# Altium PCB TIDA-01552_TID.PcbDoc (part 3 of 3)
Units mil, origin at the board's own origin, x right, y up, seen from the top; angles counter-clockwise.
Board outline 6250 x 2150 mil, 4 copper layers (Top Layer, Signal Layer 1, Signal Layer 2, Bottom Layer), stack 62.6 mil thick; 251 components, 249 nets, 926 pads, 730 vias.
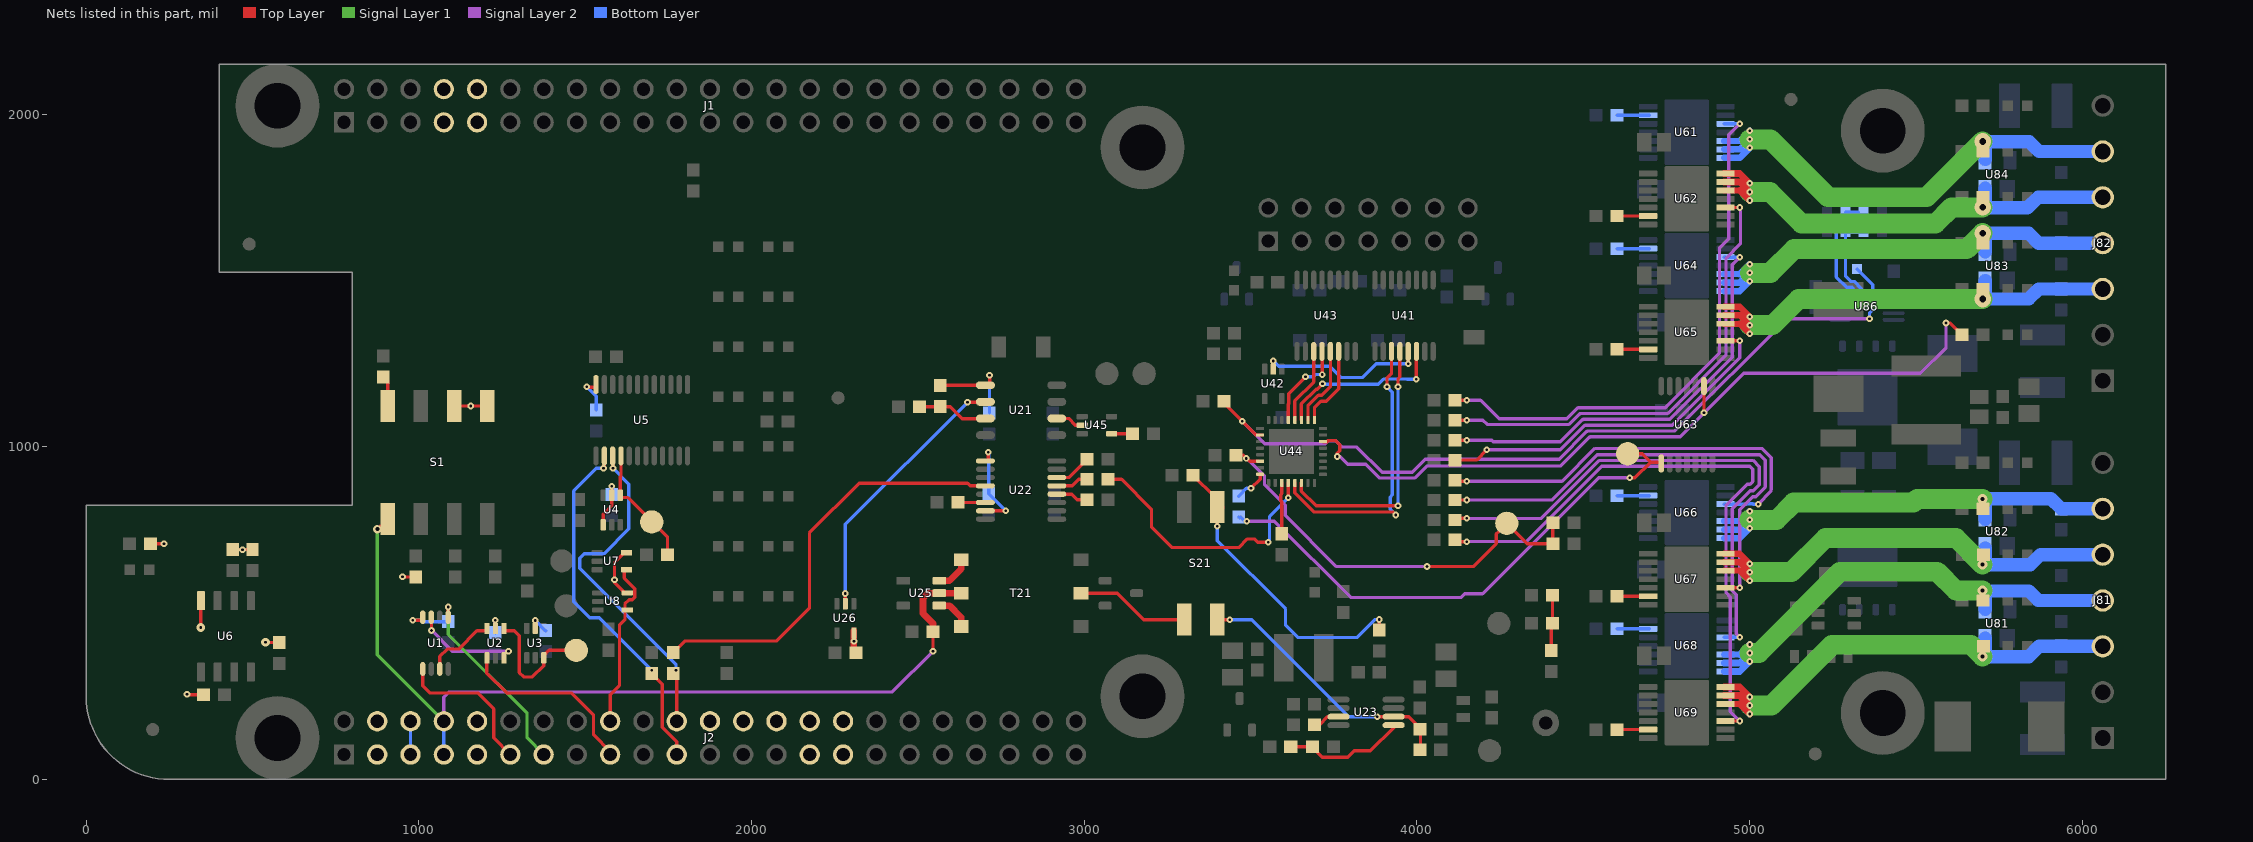
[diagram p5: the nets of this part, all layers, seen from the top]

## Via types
v1: diameter 20, hole 8, Top Layer to Bottom Layer, tented both sides, 418 vias
v2: diameter 19.68, hole 7.87, Top Layer to Bottom Layer, 77 vias
v3: diameter 30, hole 12, Top Layer to Bottom Layer, tented both sides, 73 vias
v4: diameter 19.68, hole 7.87, Top Layer to Bottom Layer, tented both sides, 48 vias
v5: diameter 39.37, hole 19.68, Top Layer to Bottom Layer, 36 vias
v6: diameter 26, hole 12, Top Layer to Bottom Layer, tented both sides, 31 vias
v7: diameter 20, hole 7.87, Top Layer to Bottom Layer, tented both sides, 12 vias
v8: diameter 20, hole 8, Top Layer to Bottom Layer, 12 vias
v9: diameter 30, hole 12, Top Layer to Bottom Layer, 9 vias
v10: diameter 32, hole 16, Top Layer to Bottom Layer, tented both sides, 8 vias
v11: diameter 50, hole 20, Top Layer to Bottom Layer, tented both sides, 4 vias
v12: diameter 26, hole 8, Top Layer to Bottom Layer, tented both sides, 2 vias

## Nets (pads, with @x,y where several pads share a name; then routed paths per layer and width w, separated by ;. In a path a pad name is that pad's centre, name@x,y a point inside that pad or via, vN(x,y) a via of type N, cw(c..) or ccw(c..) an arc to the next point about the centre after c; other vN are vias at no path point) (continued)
NetR17_2: R17.2 TP1.1 U4.4 U5.4 | length 380.6
  Top Layer w10: U5.4@1607.5,980.59 1607.5,911.5 1605.59,909.59 1605.59,847.4 1628.6,847.4 TP1.1@1700,776 ; TP1.1@1700,774 TP1.1@1700,776 ; R17.2@1747.5,675 1747.5,728.5 TP1.1@1700,776
NetR18_2: R18.2 S1.8 | length 92.4
  Top Layer w10: R18.2@893,1209.5 906,1196.5 S1.8@906,1122.5
NetR23_2: R23.2 U22.14 | length 122.1
  Top Layer w10: U22.14@2909.41,907.5 2953,907.5 R23.2@3008.5,963
NetR24_2: R24.2 U22.13 | length 107.2
  Top Layer w10: U22.13@2909.41,882.5 2963.5,882.5 2983,902 R24.2@3008.5,902
NetR25_2: R25.2 U22.12 | length 105.9
  Top Layer w10: U22.12@2909.41,857.5 2962.5,857.5 2979,841 R25.2@3008.5,841
NetR26_1: R26.1 U22.6 | length 90.3
  Top Layer w10: R26.1@2620.5,833 2621,832.5 U22.6@2710.59,832.5
NetR27_2: R27.2 R33.2 U23.5 | length 353.8
  Top Layer w10: R27.2@3633.62,98 3683.5,98 3714.6,66.43 3791.43,66.43 3811,86 3859.94,86 3929.68,155.74 U23.5@3929.68,163.3
NetR28_1: R28.1 R34.2 S21.2 U23.6 | length 809.7
  Top Layer w10: S21.2@3400,480.51 v1@3436.48,480.51 ; v1(3880.51,189) 3929.57,189 U23.6@3929.68,188.89 3975.11,188.89 4010.5,153.5 R34.2@4010.5,89
  Bottom Layer w10: v1(3437,479.99) 3504.01,479.99 3795,189 v1(3880.51,189)
NetR29_1: R29.1 R35.2 S21.3 | length 931.7
  Top Layer w10: R35.2@3326.5,915 3393.59,847.91 3393.59,841.54 3417.13,818 3400,800.87 v1(3400,761) ; R29.1@3887,449.5 v1(3887,481)
  Bottom Layer w10: v1(3400,761) 3400,717.53 3605,512.53 3605,464 3642,427 3821,427 3875,481 v1(3887,481)
NetR31_2: R31.2 U23.3 | length 82.7
  Top Layer w10: R31.2@3691.5,165 3707,165 3730.89,188.89 U23.3@3764.32,188.89
NetR43_2: R43.2 U44.11 | length 155.9
  Top Layer w10: R43.2@3593,738.5 3593.47,738.97 3593.47,834.18 3590.28,837.37 3590.28,856.32 3593.47,859.51 U44.11@3593.47,891.51
NetR44_1: R44.1 U45.4 | length 69.3
  Top Layer w10: U45.4@3075.4,1039.41 3075.81,1039 R44.1@3144.5,1039
NetR61_1: R61.1 U61.13 | length 97.3
  Bottom Layer w10: R61.1@4601.5,1996.3 U61.13@4698.76,1996.3
NetR62_1: R62.1 U62.13 | length 97.3
  Top Layer w10: R62.1@4601.5,1693.67 U62.13@4698.76,1693.67
NetR63_2: R63.2 U61.3 | length 1660.9
  Top Layer w10: R63.2@4114.5,1140 v1(4150,1140)
  Signal Layer 2 w10: v1(4150,1140) 4191,1140 4246.5,1084.5 4449.76,1084.5 4481.76,1116.5 4483.26,1116.5 4484.26,1117.5 4745.87,1117.5 4909,1280.63 4909,1597.25 4937.33,1625.58 4937.33,1938.07 v1(4970,1970.74)
  Bottom Layer w10: U61.3@4923.2,1970.74 v1(4970,1970.74)
NetR64_2: R64.2 U62.3 | length 1412.3
  Top Layer w10: R64.2@4114.5,1080 v1(4150,1080) ; U62.3@4923.2,1719.22 v1(4970,1719.22)
  Signal Layer 2 w10: v1(4150,1080) 4198,1080 4211,1067 4457.01,1067 4489.01,1099 4490.51,1099 4491.51,1100 4753.12,1100 4929,1275.88 4929,1567 4972.1,1610.1 v1@4972.1,1717.13
NetR65_2: R65.2 U44.8 | length 100.1
  Top Layer w10: v1(3501,875) 3528.51,902.51 U44.8@3528.51,917.1
  Bottom Layer w10: R65.2@3464.04,851.74 3487.3,875 v1(3501,875)
NetR66_1: R66.1 U64.13 | length 97.3
  Bottom Layer w10: R66.1@4601.5,1595.63 U64.13@4698.76,1595.63
NetR67_1: R67.1 U65.13 | length 97.3
  Top Layer w10: R67.1@4601.5,1293 U65.13@4698.76,1293
NetR68_2: R68.2 U64.3 | length 1296.7
  Top Layer w10: R68.2@4114.5,1020 v1(4150,1020)
  Signal Layer 2 w10: v1(4150,1020) 4225,1020 4229.5,1015.5 4430.25,1015.5 4496.25,1081.5 4497.76,1081.5 4498.76,1082.5 4760.37,1082.5 4947.13,1269.26 4947.13,1547.2 v1(4970,1570.07)
  Bottom Layer w10: U64.3@4923.2,1570.07 v1(4970,1570.07)
NetR69_2: R69.2 U65.3 | length 1080.8
  Top Layer w10: R69.2@4114.5,960 4179,960 v1(4210,991) ; U65.3@4923.2,1318.56 v1(4970,1318.56)
  Signal Layer 2 w10: v1(4210,991) 4430.5,991 4503.5,1064 4505.01,1064 4506.01,1065 4767.62,1065 4970,1267.38 v1(4970,1318.56)
NetR70_1: R70.1 U66.13 | length 97.3
  Bottom Layer w10: R70.1@4601.5,853.3 U66.13@4698.76,853.3
NetR71_1: R71.1 U67.13 | length 97.3
  Top Layer w10: R71.1@4601.5,550.67 U67.13@4698.76,550.67
NetR73_2: R73.2 U66.3 | length 1263.4
  Top Layer w10: R73.2@4114.5,900 4118.5,896 v1(4150,896)
  Signal Layer 2 w10: v1(4150,896) 4436.01,896 4535.01,995 5036.75,995 5064.5,967.25 5064.5,871.75 5064,871.25 5064,866 v1(5025.74,827.74)
  Bottom Layer w10: U66.3@4923.2,827.74 4989.36,827.74 4990.68,829.06 5009.32,829.06 5010.64,827.74 v1(5025.74,827.74)
NetR74_2: R74.2 U67.3 | length 1463.6
  Top Layer w10: R74.2@4114.5,840 v1(4150,840) ; U67.3@4923.2,576.22 v1(4970,576.22)
  Signal Layer 2 w10: v1(4150,840) 4404.75,840 4541.25,976.5 5030.5,976.5 5047,960 5047,879 5018.24,850.24 5009.24,850.24 4970,811 v1(4970,576.22)
NetR76_1: R76.1 U68.13 | length 97.3
  Bottom Layer w10: R76.1@4601.5,452.63 U68.13@4698.76,452.63
NetR77_1: R77.1 U69.13 | length 97.3
  Top Layer w10: R77.1@4601.5,150 U69.13@4698.76,150
NetR78_2: R78.2 U68.3 | length 1605
  Top Layer w10: R78.2@4114.5,780 4119.5,785 v1(4150,785)
  Signal Layer 2 w10: v1(4150,785) 4150.5,784.5 4374,784.5 4548.5,959 5010,959 5029,940 5029,886 5010.74,867.74 5001.74,867.74 4947.5,813.5 4947.5,566.9 4959.5,554.9 4959.5,437.57 v1(4970,427.07)
  Bottom Layer w10: U68.3@4923.2,427.07 v1(4970,427.07)
NetR79_2: R79.2 U69.3 | length 1853
  Top Layer w10: R79.2@4114.5,720 4119.5,715 v1(4150,715) ; U69.3@4923.2,175.56 v1(4970,175.56)
  Signal Layer 2 w10: v1(4150,715) 4150.5,715.5 4329.75,715.5 4555.75,941.5 5000,941.5 5009,932.5 5009,895.5 5001.03,887.53 4992.53,887.53 4929,824 4929,560.66 4942,547.66 4942,203.56 v1(4970,175.56)
NetR80_1: R80.1 R81.2 R82.2 | length 149.3
  Top Layer w10: R80.1@4404,387.5 4404,466.5 R81.2@4407.5,470 ; 4407.5,488.7 R82.2@4407.5,554
NetR92_1: R92.1 R93.2 U86.4 | length 399.1
  Bottom Layer w10: U86.4@5271.29,1440.68 5305.72,1440.68 5317.63,1452.59 5317.63,1468.15 5306.63,1479.15 5291.07,1479.15 5260.13,1510.1 5260.13,1665.33 5267.67,1672.87 5288,1672.87 R92.1@5288,1705 R93.2@5327,1705
NetR94_1: R94.1 R95.2 U86.3 | length 339.7
  Bottom Layer w10: U86.3@5271.29,1421 5277.2,1421 5277.2,1421.91 5312.22,1421.91 5335.5,1445.19 5335.5,1475.55 5314.03,1497.02 5302.98,1497.02 5288,1512 R94.1@5288,1645 R95.2@5327,1645
NetR96_2: R96.2 U86.7 | length 170.6
  Bottom Layer w10: R96.2@5323,1534 5370,1487 5370,1449 5378.31,1440.68 U86.7@5432.71,1440.68
NetS21_1: S21.1 T21.2 | length 320.9
  Top Layer w10: 3012,560 3099,560 3178.49,480.51 S21.1@3300,480.51
NetT21_4: T21.4 U25.3 | length 114.5
  Top Layer w20: U25.3@2557.24,597.4 2594.4,597.4 2630,633 T21.4@2630,660
NetT21_6: T21.6 U25.1 | length 114.5
  Top Layer w20: U25.1@2557.24,522.6 2594.4,522.6 2630,487 T21.6@2630,460
NetTP2_1: TP2.1 U2.4 U3.3 | length 383.1
  Top Layer w10: 1263.46,447.4 1287.27,447.4 1302.13,432.54 1302.13,321.53 1315.53,308.13 1341.43,308.13 1375.59,342.29 1375.59,372.6 1390.99,388 TP2.1@1473,388
NetU1_3: U1.3 U2.6 | length 202.5
  Top Layer w10: U1.3@1062.8,341.1 1062.8,369.81 1085.11,392.13 1119.41,392.13 1174.69,447.4 U2.6@1204.41,447.4
NetU1_7: U1.7 U2.3 | length 297.5
  Top Layer w10: U1.7@1037.2,487.76 1038,486.96 v1(1038,448)
  Signal Layer 2 w10: v1(1038,448) 1100.72,385.28 v1(1269.39,385.28)
NetU21_2: U21.2 U26.2 | length 831.5
  Top Layer w10: U26.2@2282,521.4 v1(2282,559) ; v1(2649,1134) 2714.51,1134 U21.2@2715.51,1135
  Bottom Layer w10: v1(2282,559) 2282,767 v1(2649,1134)
NRST: U41.13 U42.2 | length 503.1
  Top Layer w10: U42.2@3568,1243.13 v1(3568,1258) ; v1(3973.5,1250) U41.13@3973.5,1294.59
  Bottom Layer w10: v1(3568,1258) 3584,1242 3738,1242 3772,1208 3835.65,1208 3877.65,1250 v1(3973.5,1250)
P_GOOD: R46.2 U44.2 U86.8 | length 2401.6
  Top Layer w10: R46.2@3416.97,1134.47 v1(3475,1076.44) 3516.22,1035.21 U44.2@3528.51,1035.21 U44.2@3533.24,1035.21
  Signal Layer 2 w10: v1(3475,1076.44) 3542.44,1009 3724.18,1009 3733.52,1018.34 3755.5,1018.34 3774.71,999.13 3819.19,999.13 3894.82,923.5 3985.32,923.5 4024.82,963 4427.25,963 4510.75,1046.5 4512.26,1046.5 4513.26,1047.5 4774.86,1047.5 5112.36,1385 v1(5360,1385)
  Bottom Layer w10: v1(5360,1385) 5360,1401 5380,1421 U86.8@5432.71,1421
PWR_BUT: J2.9
RST_N: U21.6 U45.2 | length 104.4
  Top Layer w10: U21.6@2904.49,1085 2953,1085 2973,1065 U45.2@3000.6,1065
RXD: U41.12 U44.14 | length 807.1
  Top Layer w10: U44.14@3652.53,891.51 3652.53,866.92 3696.44,823 3709,823 v1(3943,823) ; v1(3943,1180) 3943,1204.49 3948.5,1209.99 U41.12@3948.5,1294.59
  Bottom Layer w10: v1(3943,823) v1(3943,1180)
SCLK: R5.2 U22.4 | length 1292.6
  Top Layer w10: R5.2@1764,381.5 1798.5,416 2074.78,416 2173.9,515.12 2173.9,740.9 2323,890 2649,890 2656.5,882.5 U22.4@2710.59,882.5
SCLK_ISO: R24.1 U44.12 | length 815.2
  Top Layer w10: R24.1@3071.5,902 3112,902 3201.78,812.22 3201.78,759.94 3264.6,697.13 3464.78,697.13 3490.53,722.87 3511.13,722.87 3521,713 v1(3553,713) ; v1(3613.16,846.84) U44.12@3613.16,891.51
  Bottom Layer w10: v1@3552.87,713 3556.87,717 3556.87,790.56 v1(3613.16,846.84)
SHIFTCLK: R65.1 TP61.1 U63.8 | length 1620.5
  Top Layer w10: TP61.1@4633,979 4677,979 4702.06,953.94 ; v8(4639,907) 4655.11,907 4702.06,953.94 ; U63.8@4734.23,953.94 4702.06,953.94
  Signal Layer 2 w10: v1(3488,776) 3571.44,776 3800.32,547.13 4133.13,547.13 4144,558 4197,558 4546,907 v8(4639,907)
  Bottom Layer w10: R65.1@3464.04,788.75 3466.55,786.25 3469.3,789 3482.3,776 v1(3488,776)
SHIFTSTRT: R45.2 U44.22 U63.2 | length 2328.8
  Top Layer w10: U44.22@3717.49,1015.53 3730.18,1015.53 3733.53,1018.87 3754.66,1018.87 3767.87,1005.66 3767.87,988.53 3760,980.65 v1(3760,971) ; U63.2@4862,1178.35 4862.5,1177.85 v1(4862.5,1102.5) ; v1(5590,1372) 5602.95,1372 R45.2@5638.5,1336.44
  Signal Layer 2 w10: v1(3760,971) 3767.71,971 3791.71,947 3846.57,947 3887.57,906 3992.57,906 4028.57,942 4431,942 4518,1029 4519.51,1029 4520.51,1030 4791,1030 4862,1101 4862.5,1101.5 v1(4862.5,1102.5) 4863,1102 4982,1221 5513,1221 5590,1298 v1(5590,1372)
SPI0_CS: J2.17 U2.1 | length 564.7
  Top Layer w10: U2.1@1204.41,372.6 1204.41,319.75 1264.16,260 1458,260 1525,193 1525,134 1575,84 J2.17@1575,75
SPI0_D0: J2.21 R3.1 U5.2 | length 1088.5
  Top Layer w10: v1@1557.5,937.5 U5.2@1557.5,980.59 ; R3.1@1700,318.5 1731.61,286.89 1731.61,157.03 1775,113.64 J2.21@1775,75
  Bottom Layer w10: v1(1555,935) 1533,935 1465.25,867.25 1465.25,534.21 1513.39,486.07 1542.25,486.07 v1(1700,328.33)
SPI0_D1: J2.18 U7.4 U8.4 | length 504.9
  Top Layer w10: J2.18@1575,175 1575,254.37 1603,282.37 1603,464 1619.4,480.4 1619.4,509.41 1619.4,527.52 1631.72,539.84 1641.47,539.84 1649.01,547.38 1649.01,573.8 1617.4,605.4 U7.4@1617.4,630.41
SPI0_SCLK: J2.22 R5.1 U5.3 | length 1035.9
  Top Layer w10: U5.3@1582.5,980.59 1582.5,935.99 v1(1583.49,935) ; R5.1@1764,318.5 1775,307.5 J2.22@1775,175
  Bottom Layer w10: v1(1583.49,935) 1631,887.49 1631,753 1556.5,678.5 1496.68,678.5 1483.13,664.95 1483.13,634.81 1773,344.93 v1@1773,329.25
  other v1: 1773,328
SPI1_CS0: J2.28
SPI1_D0: J2.29
SPI1_D1: J2.30
SPI1_SCLK: J2.31
SUPPLY_DIV: C66.1 R72.1 R75.2 TP62.1 U44.6 | length 1252.9
  Top Layer w10: C66.1@3455.5,975 3478.33,975 3496.85,956.47 U44.6@3523.79,956.47 ; v1(4030,640) 4168.84,640 4238,709.16 4238,738 4245.04,745.04 ; 4294.96,745.04 4331,709 R72.1@4408.5,709 R75.2@4408.5,772
  Signal Layer 2 w10: v1(3487,965) 3488.33,965 3541.75,911.58 3541.75,885.9 3603.68,823.97 3603.68,794.32 3758,640 v1(4030,640)
SYS_5V: C31.1 J2.7 J2.8 S1.1 T21.5 U25.2 | length 2666.5
  Top Layer w10: v6(875,752.5) S1.1@884,761.5 ; v1(2545.5,385.5) C31.1@2545.5,444
  Top Layer w20: C31.1@2545.5,444 2545.5,468.64 2515,499.13 2515,545.32 2529.68,560 2557.24,560 T21.5@2630,560
  Signal Layer 2 w10: J2.8@1075,175 1075,247 1091,263 2422.99,263 v1(2545.5,385.5)
  Signal Layer 1 w10: v6(875,752.5) 875,375 J2.8@1075,175
  Bottom Layer w10: J2.7@1075,75 J2.8@1075,175
SYS_RESETN: J2.10
TCK: U43.14 U44.25 | length 214.8
  Top Layer w10: U44.25@3691.9,1080.49 3691.9,1117.49 3711.28,1136.87 3726.87,1136.87 3764.5,1174.5 3764.5,1256.05
TDI/TCLK: U41.14 U44.27 | length 518.7
  Top Layer w10: U44.27@3652.53,1080.49 3652.53,1128.67 3696.48,1172.62 3699.9,1172.62 3716,1188.72 v1(3716,1189) ; v1(3998,1203) 3998,1294.09 U41.14@3998.5,1294.59
  Bottom Layer w10: v1(3716,1189) 3716.87,1188.13 3883.78,1188.13 3899.2,1203.55 3970.84,1203.55 3970.29,1203 v1(3998,1203)
TDO: U43.11 U44.28 | length 237.6
  Top Layer w10: U44.28@3632.84,1080.49 3632.84,1137.84 3689.5,1194.5 U43.11@3689.5,1294.59
TEST: U43.12 U44.29 | length 281.7
  Top Layer w10: U44.29@3613.16,1080.49 3613.16,1128.35 3614.34,1129.53 3614.34,1159.34 v1(3665,1210) ; U43.12@3714.5,1294.59 3715,1294.09 v1(3715,1217)
  Bottom Layer w10: v1(3665,1210) 3686.5,1210 3693.5,1217 v1(3715,1217)
TIMER4: J1.7
TIMER5: J1.9
TIMER6: J1.10
TIMER7: J1.8
TMS: U43.13 U44.26 | length 248.2
  Top Layer w10: U44.26@3672.21,1080.49 3672.21,1123.08 3703.88,1154.75 3714.1,1154.75 3739.83,1180.48 3739.83,1294.26 U43.13@3739.5,1294.59
TXD: U41.11 U44.13 | length 882
  Top Layer w10: U44.13@3632.84,891.51 3632.84,861.32 3690.17,804 3927,804 v1(3936,795) ; v1(3910,1180) 3910,1207 3923.5,1220.5 U41.11@3923.5,1294.59
  Bottom Layer w10: v1(3910,1180) 3925.5,1164.5 3925.5,855.22 3919.13,848.85 3919.13,811.87 v1(3936,795)
UART1_RXD: J2.26
UART1_TXD: J2.24
UART4_RXD: J2.11 U1.1 | length 459.6
  Top Layer w10: U1.1@1011.61,341.1 1011.61,281.39 1033,260 1177,260 1225,212 1225,125 J2.11@1275,75
UART4_TXD: J2.13 U1.5 | length 602.1
  Top Layer w10: U1.5@1088.39,478.9 v1(1088.39,518.61)
  Signal Layer 1 w10: v1(1088.39,518.61) 1088.39,435.78 1325,199.16 1325,125 J2.13@1375,75
VDD_3V3B: C1.1 C2.1 C3.1 C4.1 C5.1 C6.1 C21.1 C23.1 J2.3 J2.4 R4.2 R8.2 R11.2 R12.2 R13.2 R21.2 R22.2 S1.5 S1.6 U1.8 U2.5 U3.5 U4.1 U4.5 U5.24 U6.8 U7.5 U8.5 U21.1 U22.1 U22.7 U26.5 | length 1655.3
  Top Layer w10: R4.2@193.5,709 v1(234,709) ; v1@304,255 R8.2@352.5,255 ; v12(344,457) 344,523.49 U6.8@345,524.49 ; R12.2@440,691.5 R13.2@481.3,691.5 ; v12@539.5,411.5 C6.1@580,411.5 ; v1(951,609) 951.5,608.5 R11.2@990,608.5 ; v1@982.1,478.9 U1.8@1011.61,478.9 ; S1.6@1106,1122.5 S1.5@1184,1122.5 ; U2.5@1230,447.4 v1(1230,479) ; U3.5@1350,447.4 v1(1350,478) ; v1@1505.59,1179.41 U5.24@1532.5,1179.41 ; U4.1@1554.43,765 1554.41,797.41 1580,823 1580,847.4 v1(1580,881) ; U7.5@1617.4,681.59 1587.8,651.98 1587.8,592.2 U8.5@1619.4,560.59 ; R21.2@2307.59,386.91 R21.2@2313.5,381 ; R22.2@2567,1185 2715.51,1185 v1@2715.51,1214.49 ; U22.7@2710.59,807.5 v1(2764.42,807.5) ; U22.1@2710.59,957.5 2711,957.91 v1(2711,984)
  Top Layer w20: R21.2@2307.59,386.91 U26.5@2307.59,446.6
  Bottom Layer w10: v1@982.1,478.9 1011.61,478.9 1016.02,474.5 C1.1@1088.39,474.5 ; v1(1230,479) 1230,441.56 C2.1@1230.07,441.49 ; v1(1350,478) 1380.5,447.5 C3.1@1382,447.5 ; v1(1505,1180) 1533,1152 C5.1@1533,1110.5 ; v1@2712.49,982.51 C23.1@2712.49,859.02 v1@2764,807.5 ; C21.1@2715,1101.5 v1(2715,1215)
  other v1: 303,256 2308,415 982,479 1587.8,600 470,691 1156,1122.5
  other v12: 539,412
VDD_5V: J2.5 J2.6 | length 100
  Bottom Layer w10: J2.5@975,75 J2.6@975,175
VDD_ADC: J2.32
XRST_N: R2.2 R22.1 U21.3 | length 228.5
  Top Layer w10: R2.2@2504.5,1120 R22.1@2565.5,1120 ; R22.1@2567,1121.5 R22.1@2565.5,1120 ; U21.3@2715.51,1085 2714.51,1084 2632.66,1084 2596.66,1120 R22.1@2565.5,1120
Y0: C81.1 J81.3 R83.2 U69.5 U69.6 U69.7 U81.2 | length 1478.3
  Top Layer w18: U69.5@4923.2,226.74 4970,226.74
  Top Layer w20: U69.6@4923.2,252.33 4968.67,252.33 v1@4999,222 ; U69.7@4923.2,277.92 4970,277.92 v1(5000,247.92) ; 4970,226.74 v1(5000,196.74)
  Signal Layer 1 w60: v1@5000.33,222 5065,222 5248,405 5665.2,405 v3(5700,370.2)
  Bottom Layer w40: U81.2@5707.5,424.69 5707.5,369.26 5838.26,369.26 5869.5,400.5 C81.1@5936,400.5 ; C81.1@5936.29,400.2 J81.3@6061,400.2
  other v1: 5000,222.33
Y1: C82.1 J81.4 R84.2 U68.5 U68.6 U68.7 U81.3 | length 1512.7
  Signal Layer 1 w60: v1(5000,380.3) 5027.59,380.3 5271.67,624.38 5563.62,624.38 5620,568 v3(5700,568)
  Bottom Layer w18: U68.5@4923.2,375.89 4970,375.89
  Bottom Layer w20: U68.7@4923.2,324.71 4970,324.71 v1(5000,354.71) ; U68.6@4923.2,350.3 4970,350.3 v1(5000,380.3) ; 4970,375.89 v1(5000,405.89)
  Bottom Layer w40: U81.3@5707.5,511.31 5707.5,566.74 5838.26,566.74 5866.84,538.16 C82.1@5936,538.16 ; C82.1@5936.16,538 J81.4@6061,538
Y2: C83.1 J81.5 R85.2 U67.5 U67.6 U67.7 U82.2 | length 1460.3
  Top Layer w18: U67.5@4923.2,627.41 4970,627.41
  Top Layer w20: U67.6@4923.2,653 4970,653 v1(5000,623) ; U67.7@4923.2,678.59 4970,678.59 v1(5000,648.59) ; 4970,627.41 v1(5000,597.41)
  Signal Layer 1 w60: v1(5000,623) 5125,623 5227.83,725.83 5619.97,725.83 v3(5700,645.8)
  Bottom Layer w40: U82.2@5707.5,695.69 5707.5,645 5843,645 5873.83,675.83 C83.1@5936,675.83 ; C83.1@5936,675.83 J81.5@6061,675.8
Y3: C84.1 J81.6 R86.2 U66.5 U66.6 U66.7 U82.3 | length 1420.9
  Signal Layer 1 w60: v1(5000,780.97) 5005.34,780.97 5006.06,780.24 5080.24,780.24 5132,832 5492,832 5503.59,843.59 v3(5700,843.59)
  Bottom Layer w18: U66.5@4923.2,776.56 4970,776.56
  Bottom Layer w20: U66.7@4923.2,725.38 4970,725.38 v1(5000,755.38) ; U66.6@4923.2,750.97 4970,750.97 v1(5000,780.97) ; 4970,776.56 v1(5000,806.56)
  Bottom Layer w40: U82.3@5707.5,782.31 U82.3@5707.5,788.31 5707.5,844 5905.5,844 C84.1@5936,813.5 ; C84.1@5937.09,813.59 J81.6@6061,813.59
Y4: C85.1 J82.3 R87.2 U65.5 U65.6 U65.7 U83.2 | length 1421.7
  Top Layer w18: U65.5@4923.2,1369.74 4970,1369.74
  Top Layer w20: U65.6@4923.2,1395.33 4970,1395.33 v1(5000,1365.33) ; U65.7@4923.2,1420.92 4970,1420.92 v1(5000,1390.92) ; 4970,1369.74 v1(5000,1339.74)
  Signal Layer 1 w60: v1(5000,1365.33) 5068.33,1365.33 5147.2,1444.2 v11(5700,1444.2)
  Bottom Layer w40: U83.2@5707.5,1499.69 5707.5,1444.26 5838.26,1444.26 5868.2,1474.2 J82.3@6061,1474.2
Y5: C86.1 J82.4 R88.2 U64.5 U64.6 U64.7 U83.3 | length 1437.2
  Signal Layer 1 w60: v1@5001,1523 5062,1523 5133,1594 5652,1594 v11(5700,1642)
  Bottom Layer w18: U64.5@4923.2,1518.89 4970,1518.89
  Bottom Layer w20: U64.7@4923.2,1467.71 4970,1467.71 v1(5000,1497.71) ; U64.6@4923.2,1493.3 4970,1493.3 v1(5000,1523.3) ; 4970,1518.89 v1(5000,1548.89)
  Bottom Layer w40: U83.3@5707.5,1586.31 5707.5,1641.74 5838.26,1641.74 5868,1612 J82.4@6061,1612
Y6: C87.1 J82.5 R89.2 U62.5 U62.6 U62.7 U84.2 | length 1452.6
  Top Layer w18: U62.5@4923.2,1770.41 4970,1770.41
  Top Layer w20: U62.6@4923.2,1796 4970,1796 v1(5000,1766) ; U62.7@4923.2,1821.59 4970,1821.59 v1(5000,1791.59) ; 4970,1770.41 v1(5000,1740.41)
  Signal Layer 1 w60: v1(5000,1766) 5061,1766 5156,1671 5558.39,1671 5607.18,1719.8 v11(5700,1719.8)
  Bottom Layer w40: U84.2@5707.5,1776.69 U84.2@5707.5,1774.69 5707.5,1718 5835,1718 5866.8,1749.8 J82.5@6061,1749.8
Y7: C88.1 J82.6 R90.2 U61.5 U61.6 U61.7 U84.3 | length 1528.3
  Signal Layer 1 w60: v1(5000,1923.97) 5062.03,1923.97 5236,1750 5531.59,1750 v11@5699.59,1918
  Bottom Layer w18: U61.5@4923.2,1919.56 4970,1919.56
  Bottom Layer w20: U61.7@4923.2,1868.38 4970,1868.38 v1(5000,1898.38) ; U61.6@4923.2,1893.97 4970,1893.97 v1(5000,1923.97) ; 4970,1919.56 v1(5000,1949.56)
  Bottom Layer w40: U84.3@5707.5,1863.31 5707.5,1917 5840,1917 5869.41,1887.59 J82.6@6061,1887.59
  other v11: 5700,1917.59
pads on no net: D41.2 D42.2 FID1.1 FID2.1 FID3.1 FID4.1 FID5.1 J41.4 J41.6 LBL1.0 MH1.1 MH2.1 MH3.1 MH4.1 MH5.1 MH6.1 Q81.9@5296.03,614.44 Q81.9@5296.03,680.58 Q81.9@5353.91,614.44 Q81.9@5353.91,680.58 Q81.9@5411.78,614.44 Q81.9@5411.78,680.58 Q82.9@5296.03,1132.47 Q82.9@5296.03,1198.61 Q82.9@5353.91,1132.47 Q82.9@5353.91,1198.61 Q82.9@5411.78,1132.47 Q82.9@5411.78,1198.61 U26.1 U42.1 U44. U44.4 U44.17 U44.20 U44.31 U45.1 U61.1 U61.4 U61.11 U61.15@4811,1945.15 U62.1 U62.4 U62.11 U62.15@4811,1744.81 U64.1 U64.4 U64.11 U64.15@4811,1544.48 U65.1 U65.4 U65.11 U65.15@4811,1344.15 U66.1 U66.4 U66.11 U66.15@4811,802.15 U67.1 U67.4 U67.11 U67.15@4811,601.81 U68.1 U68.4 U68.11 U68.15@4811,401.48 U69.1 U69.4 U69.11 U69.15@4811,201.15
copper on no net:
  other v5: 575,27.56 490.61,76.28 659.39,76.28 5400,102.56 5315.61,151.28 5484.39,151.28 3175,152.56 490.61,173.72 659.39,173.72 3090.61,201.28 3259.39,201.28 575,222.44 5315.61,248.72 5484.39,248.72 5400,297.44 3090.61,298.72 3259.39,298.72 3175,347.44 3175,1802.56 3090.61,1851.28 3259.39,1851.28 5400,1852.56 5315.61,1901.28 5484.39,1901.28 575,1927.56 3090.61,1948.72 3259.39,1948.72 490.61,1976.28 659.39,1976.28 3175,1997.44 5315.61,1998.72 5484.39,1998.72 5400,2047.44 490.61,2073.72 659.39,2073.72 575,2122.44

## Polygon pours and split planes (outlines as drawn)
24V_Field on Top Layer "Top-24V_Raw" (solid, pour order 60): 5366,1148 5366,415 5862,415 5862,848 6126,848 6126,1148
NetD89_2 on Top Layer "Top-TVS" (solid, remove dead copper, pour order 67): 5784,245 5784,0 5510,0 5510,245
24V_LOCAL on Top Layer "Top-24V_Local" (solid, pour order 47): 5387,1354 5387,980 5150,980 5150,1354
DGND on Top Layer "Top Layer-DGND" (solid, remove dead copper, pour order 74): 20,2130 20,20 3330,20 3330,2130
GND_DEBUG on Top Layer "Top-GND_Debug" (solid, remove dead copper, pour order 65): 3350,1770 3350,1400 4370,1400 4370,1770
24V_Field on Top Layer "Top-24V_Raw" (solid, pour order 66): 5859,2150 5859,1935 6126,1935 6126,2150
GND_SIGNAL on Top Layer "Top-GND_Signal" (solid, remove dead copper, pour order 75): 2790,0 2790,2150 6250,2150 6250,0
+3.3V_ISO on Signal Layer 1 "Sig2-3.3V_Iso" (solid, pour order 82): 2820,1390 4060,1390 4060,0 3350,0 3350,420 2820,420
24V_Field on Signal Layer 1 "Sig1-24V_RAW" (solid, remove dead copper, pour order 64): 6250,2150 5890,2150 5890,376 6250,376
24V_LOCAL on Signal Layer 1 "Sig2-24V_Local" (solid, remove dead copper, pour order 46): 4100,0 5935,0 5935,2150 3337,2150 3337,1774 4100,1774
DGND on Signal Layer 1 "S1 Layer-DGND" (solid, remove dead copper, pour order 70): 20,2130 20,20 3330,20 3330,2130
GND_DEBUG on Signal Layer 1 "Sig1-GND_Debug" (solid, remove dead copper, pour order 73): 3350,1770 3350,1400 4370,1400 4370,1770
GND_SIGNAL on Signal Layer 1 "Sig1-GND_Signal" (solid, remove dead copper, pour order 44): 6250,0 6250,374.99 5090,375.02 5090,0
+3.3V_ISO on Signal Layer 2 "Sig2-3.3V_Iso" (solid, remove dead copper, pour order 72): 2820,1390 4060,1390 4060,0 3350,0 3350,420 2820,420
GND_EARTH on Signal Layer 2 "Earth_Shield" (solid, remove dead copper, pour order 45): 5900,2150 6250,2150 6250,0 5900,0
NetD89_2 on Signal Layer 2 "Sig1-TVS" (solid, remove dead copper, pour order 62): 5690,2150 5891,2150 5891,77 5796,77 5690,77
24V_LOCAL on Signal Layer 2 "Sig2-24V_Local" (solid, remove dead copper, pour order 81): 4100,0 5700,0 5700,2150 3337,2150 3337,1774 4100,1774
VDD_3V3B on Signal Layer 2 "S2 Layer-3_3V" (solid, remove dead copper, pour order 69): 20,2130 20,20 3330,20 3330,2130
+3.3V_TOOL on Signal Layer 2 "Sig2-3.3V_Tool" (solid, remove dead copper, pour order 71): 3350,1770 3350,1400 4370,1400 4370,1770
GND_SIGNAL on Signal Layer 2 "Sig1-GND_Signal" (solid, remove dead copper, pour order 63): 5891,5 5891,888.98 5016,888.98 5016,5
24V_Field on Bottom Layer "Bottom-24V_Raw" (solid, pour order 79): 5883,2091 5994,2091 5994,1971 5883,1971
24V_Field on Bottom Layer "Bottom-24V_Raw" (solid, remove dead copper, pour order 80): 5883,1040 5994,1040 5994,895 5883,895
NetD89_2 on Bottom Layer "Bottom-TVS" (solid, remove dead copper, pour order 54): 5727,737 5727,646.26 5888,646.26 5888,737
24V_Field on Bottom Layer "Bottom-TVS_C89" (solid, remove dead copper, pour order 48): 5494,1080 5701.99,1080 5702.01,825 5494,825
24V_Field on Bottom Layer "Bottom-Q81_C89_1" (solid, remove dead copper, pour order 50): 5315,574 5315,455 5600,455 5600,574
NetD89_2 on Bottom Layer "Bottom-TVS" (solid, pour order 55): 5727,1810 5727,1721.26 5888,1721.26 5888,1810
NetD89_2 on Bottom Layer "Bottom-TVS" (solid, remove dead copper, pour order 56): 5727,1535 5727,1444.26 5888,1444.26 5888,1535
NetD89_2 on Bottom Layer "Bottom-TVS" (solid, remove dead copper, pour order 57): 5727,468 5727,369.26 5888,369.26 5888,468
24V_LOCAL on Bottom Layer "Bottom-24V_Local" (solid, remove dead copper, pour order 58): 5727,566.74 5727,476 5888,476 5888,566.74
24V_LOCAL on Bottom Layer "Bottom-24V_Local" (solid, pour order 59): 5727,837.74 5727,752 5888,752 5888,837.74
24V_LOCAL on Bottom Layer "Bottom-24V_Local" (solid, remove dead copper, pour order 61): 5727,1641.74 5727,1551 5888,1551 5888,1641.74
24V_LOCAL on Bottom Layer "Bottom-24V_Local" (solid, remove dead copper, pour order 68): 5727,1918.74 5727,1825 5888,1825 5888,1918.74
GND_SIGNAL on Bottom Layer "Bottom/GND_Signal" (solid, remove dead copper, pour order 78): 3550,1060 3697,1060 3697,913 3550,913
DGND on Bottom Layer "Bottom Layer-DGND" (solid, remove dead copper, pour order 53): 20,2130 20,20 3330,20 3330,2130
GND_EARTH on Bottom Layer "Bottom-Earth" (solid, remove dead copper, pour order 52): 5731.02,2149.54 6250,2149.54 6250,0 5731.02,0
24V_LOCAL on Bottom Layer "Bottom-24V_Local" (solid, remove dead copper, pour order 42): 5393,1243 5393,1359 5180,1359 5180,1358 5151,1329 5151,1243 5219,1243
NetQ82_5 on Bottom Layer "Bottom-Q82" (solid, remove dead copper, pour order 43): 5661.46,1230 5661.46,933 5239,933 5155,1017 5155,1230
NetC99_1 on Bottom Layer "Bottom-Q81" (solid, remove dead copper, pour order 51): 5156,870 5156,382 5629,382 5629,870
GND_SIGNAL on Bottom Layer "Bottom-GND_Signal" (solid, remove dead copper, pour order 76): 2790,0 2790,2150 5730,2150 5730,0
GND_DEBUG on Bottom Layer "Bottom-GND_Debug" (solid, remove dead copper, pour order 77): 3350,1770 3350,1400 4370,1400 4370,1770
GND_SIGNAL on Bottom Layer "Bottom-GND_Signal" (solid, remove dead copper, pour order 49): 5549.93,1248 5549.93,1397 6145.93,1397 6145.93,1248

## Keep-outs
Keep-Out Layer:
  lines w10: -5,825 cw(c0,825) 0,830 ; -5,825 cw(c0,825) 0,830 ; -5,825 -5,250 ccw(c250,250) 250,-5 6250,-5 ; 0,830 795,830 795,1520 400,1520 ; 395,1525 ccw(c400,1525) 400,1520 ; 395,1525 ccw(c400,1525) 400,1520 ; 395,1525 395,2150 ; 395,2150 cw(c400,2150) 400,2155 ; 395,2150 cw(c400,2150) 400,2155 ; 400,2155 6250,2155 ; 6250,-5 ccw(c6250,0) 6255,0 ; 6250,-5 ccw(c6250,0) 6255,0 ; 6250,2155 cw(c6250,2150) 6255,2150 ; 6250,2155 cw(c6250,2150) 6255,2150 ; 6255,0 6255,2150
  text ".Layer_Name" at 577,-858.49 h60

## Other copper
Top Layer:
  rectangle net 24V_LOCAL: 4650,342.74 4687.43,384.03
  rectangle net 24V_LOCAL: 4650,743.62 4687.43,784.92
  rectangle net 24V_LOCAL: 4650,1486.07 4687.43,1527.36
  rectangle net 24V_LOCAL: 4650,1886.7 4687.43,1928
  pour cut-out: 2173,1479 2552.93,1478.98 2553,1244 2173,1244
  pour cut-out: 3320,2150 3320,1420 2790,1420 2790,390 3320,390 3320,0 3360,0 3360,430 2830,430 2830,1380 4390,1380 4390,1420 3360,1420 3360,1750 4350,1750 4350,1420 4390,1420 4390,1750 4390,1790 3360,1790 3360,2150
  text ".CopyrightYear" at 2308,1384 h60
  text "©" at 2203,1379 h105
  text "TI" at 2208,1279 h60
  text ".Layer_Name" at 577,-858.49 h60
Signal Layer 2:
  pour cut-out: 3320,2150 3320,1420 2790,1420 2790,390 3320,390 3320,0 3360,0 3360,430 2830,430 2830,1380 4390,1380 4390,1420 3360,1420 3360,1750 4350,1750 4350,1420 4390,1420 4390,1750 4390,1790 3360,1790 3360,2150
Signal Layer 1:
  pour cut-out: 3320,2150 3320,1420 2790,1420 2790,390 3320,390 3320,0 3360,0 3360,430 2830,430 2830,1380 3113.63,1380 4390,1380 4390,1420 3360,1420 3360,1750 4350,1750 4350,1420 4390,1420 4390,1750 4390,1790 3360,1790 3360,2150
Bottom Layer:
  rectangle net 24V_LOCAL: 4650,1760.67 4684.67,1800.33
  rectangle net 24V_LOCAL: 4650,1360 4684.67,1399.66
  rectangle net 24V_LOCAL: 4650,617.67 4684.67,657.33
  rectangle net 24V_LOCAL: 4650,217 4684.67,256.66
  pour cut-out: 3320,2150 3320,1420 2790,1420 2790,390 3320,390 3320,0 3360,0 3360,430 2830,430 2830,1380 4390,1380 4390,1420 3360,1420 3360,1750 4350,1750 4350,1420 4390,1420 4390,1750 4390,1790 3360,1790 3360,2150
  text "MADE IN GERMANY" at 4236.28,2054.98 h60
  text "UL94V-0" at 3766,1979 h60
  text ".Layer_Name" at 577,-858.49 h60

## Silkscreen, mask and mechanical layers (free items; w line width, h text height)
Top Overlay:
  lines w10: 3320,0 3320,390 2790,390 2790,1420 3320,1420 3320,2150 ; 3359.73,2150 3359.73,1790 4390,1790 4390,1380 3430,1380 2830,1380 2830,430 3360,430 3360,30 3360,0 ; 4058,1390 4059,1391 ; 3360,1420 3360,1750 4350,1750 4350,1420 3472,1420 3360,1420
  text "+24" at 5896.8,2005.39 h40
  text "Y7" at 5936.79,1867.6 h40
  text "P8-Header" at 2140,1830 h60
  text "Y6" at 5936.79,1729.8 h40
  text "Y5" at 5936.79,1592.01 h40
  text "Y4" at 5936.79,1454.21 h40
  text "Isolated" at 4273,1439 h40 r90
  text "Debug" at 4327,1439 h40 r90
  text "500V" at 3243,1438 h40 r90
  text "Isolation" at 3297,1438 h40 r90
  text "3.3V" at 2950,1320 h40
  text "RESET" at 3122,1320 h40
  text "GND" at 5896.8,1316 h40
  text "WR" at 945,1180 h60
  text "A1" at 1070,1180 h60
  text "A0" at 1180,1180 h60
  text "E" at 5953,1178.62 h40
  text "1" at 1315,980 h60
  text "+24" at 5896.8,931.39 h40
  text "0" at 1307,884 h60
  text "SUPPLY_DIV" at 4165,880 h40
  text "Y3" at 5936.79,793.6 h40
  text "VLED" at 640,697 h60
  text "On" at 3146,695 h40
  text "Y2" at 5936.79,655.8 h40
  text "Off" at 3126,637 h40
  text "1=on" at 639,614 h60
  text "CSENSE" at 4080,567 h40
  text "0=off" at 630,535 h60
  text "Y1" at 5950.12,518.01 h40
  text "Y0" at 5936.79,380.21 h40
  text "GND" at 5896,298 h40
  text "P9-Header" at 2140,260 h60
  text "E" at 5979,168 h40
  text "24V" at 4431,49 h40
  text ".Layer_Name" at 577,-858.49 h60
Bottom Overlay:
  text ".Layer_Name" at 577,-858.49 h60
Top Paste:
  text ".Layer_Name" at 577,-858.49 h60
Bottom Paste:
  text ".Layer_Name" at 577,-858.49 h60
Top Solder:
  text ".Layer_Name" at 577,-858.49 h60
  text ".Layer_Name" at 577,-858.49 h60
Bottom Solder:
  text ".Layer_Name" at 577,-858.49 h60
Drill Guide:
  text ".Layer_Name" at 577,-858.49 h60
M1 Board Outline:
  the board outline again, w10
  text ".Layer_Name" at 577,-858.49 h60
M2 Board Dimensions:
  rectangle: 0,-285.5 125,-160.5
  rectangle: 125,-410.5 500,-285.5
  lines w7: 0,-285.5 1000,-285.5 ; 125,-410.5 125,-160.5 ; 250,-410.5 250,-160.5 ; 500,-410.5 500,-160.5 ; 750,-410.5 750,-160.5 ; 0,-410.5 1000,-410.5 1000,-160.5 0,-160.5 0,-410.5
  text ".Layer_Name" at 577,-858.49 h60
M3 3D STEP Top:
  pour cut-out: 5720,1227 6142,1227 6142,1381 5720,1381
  text ".Layer_Name" at 577,-858.49 h60
M4 3D STEP Bottom:
  text ".Layer_Name" at 577,-858.49 h60
M5 Assembly Top:
  lines w10: -292,-930.17 6308,-930.17 ; -292,-726.83 6310,-726.83 ; -292,-523.5 -292,-1133.5 3713,-1133.5 6310,-1133.5 6310,-523.5 -291.5,-523.5 -291.5,-1133.5 1284,-1133.5 ; 2173,-1133.5 2173,-523.5 ; 3440,-726.83 3440,-523.5 ; 4280,-726.83 4280,-523.5 ; 4902,-1140 4902,-937.17
  text "COMPONENTS MARKED 'DNP' SHOULD NOT BE POPULATED." at 1153.5,-318.5 h60
  text "ASSEMBLY VARIANT:" at 1153,-434 h60
  text ".VariantName" at 2189,-434 h60
  text "PCB VIEWED FROM TOP SIDE" at -228.5,-655.67 h60
  text "BOARD #:" at 2248,-655.67 h60
  text ".PRJ_Number" at 2793.5,-655.67 h60
  text "REV:" at 3638,-655.67 h60
  text ".PCB_Rev" at 3929.5,-655.67 h60
  text "SVN REV:" at 4476,-655.67 h60
  text ".VersionControl_RevNumber" at 4982,-655.67 h60
  text "IGNORE ->" at -228.5,-858.49 h60
  text "PLOT NAME =" at -228.5,-1064.34 h60
  text ".plot_File_Name" at 577,-1064.34 h60
  text "GENERATED    :" at 2250,-1064.34 h60
  text ".Print_Date" at 3119.5,-1064.34 h60
  text ".Print_Time" at 3848.5,-1064.34 h60
  text "TEXAS INSTRUMENTS" at 5113,-1064.34 h60
M6 Assembly Bottom:
  lines w10: -292.5,-727.33 6309.5,-727.33 ; -290.5,-930.67 6309.5,-930.67 ; 1115.5,-1140.5 1115.5,-937.67 ; 1737.5,-727.33 1737.5,-524 ; 2577.5,-727.33 2577.5,-524 ; 3844.5,-1134 3844.5,-524 ; 4733.5,-1134 6309,-1134 6309,-524 -292.5,-524 -292.5,-1134 2304.5,-1134 6309.5,-1134 6309.5,-524
  text "COMPONENTS MARKED 'DNP' SHOULD NOT BE POPULATED." at 6102,-318 h60
  text ".VariantName" at 5058,-434 h60
  text "ASSEMBLY VARIANT:" at 6097,-434 h60
  text ".VersionControl_RevNumber" at 1035.5,-656.17 h60
  text "SVN REV:" at 1541.5,-656.17 h60
  text ".PCB_Rev" at 2088,-656.17 h60
  text "REV:" at 2379.5,-656.17 h60
  text ".PRJ_Number" at 3224,-656.17 h60
  text "BOARD #:" at 3769.5,-656.17 h60
  text "PCB VIEWED FROM BOTTOM SIDE" at 6246,-656.17 h60
  text "IGNORE ->" at 2547.85,-858.49 h60
  text "TEXAS INSTRUMENTS" at 904.5,-1064.84 h60
  text ".Print_Time" at 2169,-1064.84 h60
  text ".Print_Date" at 2898,-1064.84 h60
  text "GENERATED    :" at 3767.5,-1064.84 h60
  text ".plot_File_Name" at 5440.5,-1064.84 h60
  text "PLOT NAME =" at 6246,-1064.84 h60
M9 Title Sheet:
  drawing of 57 lines, arcs and shapes, not listed
  text "1" at 739.84,8036.5 h70
  text "2" at 3235.5,8036.5 h70
  text "3" at 5724.84,8036.5 h70
  text "4" at 8231.51,8036.5 h70
  text "5" at 10730.5,8036.5 h70
  text "6" at 13235.5,8036.5 h70
  text "A" at -416.5,6893.5 h70
  text "A" at 14383.5,6893.5 h70
  text "B" at -416.5,4513.5 h70
  text "B" at 14383.5,4513.5 h70
  text "C" at -416.5,2138.5 h70
  text "C" at 14383.5,2138.5 h70
  text "PROJECT TITLE:" at 11343.5,277.5 h45
  text ".PRJ_Title" at 11393.5,144.17 h70
  text "DESIGNED FOR:" at 11343.5,-23.5 h45
  text ".PRJ_Customer" at 11393.5,-163.5 h70
  text "D" at -416.5,-231.5 h70
  text "D" at 14383.5,-231.5 h70
  text "FILE NAME:" at 11343.5,-323.5 h45
  text ".PCB_File_Name_No_Path" at 11393.5,-443.5 h70
  text "Texas Instruments (TI) and/or its licensors do not warrant the accuracy or completeness of this specification" at 6374,-605.34 h45
  text "ENGINEER:" at 11343.5,-613.5 h45
  text "LAYOUT BY:" at 12848.5,-613.5 h45
  text "or any information contained therein. TI and/or its licensors do not warrant that this design will meet" at 6329.01,-718 h45
  text ".PRJ_Engineer" at 11393.5,-768.49 h70
  text ".PCB_Layout" at 12899,-768.49 h70
  text "the specifications, will be suitable for your application or fit for any particular purpose, or will operate in" at 6329.01,-830.67 h45
  text ".Layer_Name" at 577,-858.49 h60
  text "ALTIUM DESIGNER VERSION:" at 12848.5,-923.5 h45
  text "an implementation. TI and/or its licensors do not warrant that the design is production worthy. You should" at 6329.01,-943.33 h45
  text "completely validate and test your design implementation to confirm the system functionality for your application." at 6374,-1056 h45
  text ".print_Scale" at 11393.5,-1056.83 h70
  text ".Application_BuildNumber" at 12899,-1056.83 h70
  text "1" at 739.84,-1263.5 h70
  text "2" at 3235.5,-1263.5 h70
  text "3" at 5724.84,-1263.5 h70
  text "4" at 8231.51,-1263.5 h70
  text "5" at 10730.5,-1263.5 h70
  text "6" at 13235.5,-1263.5 h70
M10 Fab Notes:
  drawing of 185 lines, arcs and shapes, not listed
  text "DESIGN INFORMATION" at 12381.02,5910 h60
  text "MIN. TRACK WIDTH:" at 11736.46,5730 h60
  text "8" at 12832.7,5730 h60
  text "MIL" at 12987.46,5730 h60
  text "MIN. CLEARANCE:" at 11736.46,5598 h60
  text "0.2" at 12772.7,5598 h60
  text "mm" at 12987.46,5598 h60
  text "MIN. VIA PAD SIZE:" at 11736.46,5466 h60
  text "24" at 12802.71,5466 h60
  text "MIL" at 12987.46,5466 h60
  text "0.05mm (2MIL)" at 12431.46,5324.29 h60
  text "MINIMUM ANNULAR RING" at 11407.23,5320 h60
  text "EXTERNAL" at 13139.46,5320 h60
  text "PER" at 11607.23,5202 h60
  text "IPC-D-275 CLASS 2 LEVEL C" at 11827.23,5202 h60
  text "MIL, HOLES" at 13315.46,5089.71 h60
  text "+/-" at 12923,5089 h60
  text "+/-" at 13777,5089 h60
  text "REGISTRATION TOLERANCES:" at 11407.23,5084 h60
  text "METAL" at 12607,5084 h60
  text "5" at 13183.2,5084 h60
  text "3" at 14016.2,5084 h60
  text "MIL" at 14132.46,5084 h60
  text "MATERIAL:" at 11332.46,4874.54 h60
  text "FR-4 High Tg" at 12318.9,4734.21 h60
  text "FR-408" at 11753.46,4725.64 h60
  text "X" at 12165.46,4725.64 h60
  text "OTHER" at 13241.46,4725.64 h60
  text "62 MIL (1.6mm) +/-10%" at 12073.56,4562.92 h60
  text "THICKNESS:" at 11407.23,4558.64 h60
  text "X" at 11945.4,4558.64 h60
  text "OTHER" at 13358.46,4558.64 h60
  text "TOLERANCE:" at 11407.23,4400.64 h60
  text "X" at 12246.53,4400.64 h60
  text "ANSI IPC-6012 TYPE 3 CLASS 2" at 12433.48,4400.64 h60
  text "OTHER +/-" at 12433.46,4244.64 h60
  text "BOW & TWIST:" at 11407.23,4087.64 h60
  text "X" at 12246.53,4087.64 h60
  text "ANSI IPC-6012 TYPE 3 CLASS 2" at 12433.48,4087.64 h60
  text "OTHER +/-" at 12433.46,3929.13 h60
  text "DRILLING:" at 11332.46,3790.64 h60
  text "REFERENCE:" at 11407.23,3673.64 h60
  text "X" at 12055.46,3673.64 h60
  text "AS SHOWN" at 12242.46,3673.64 h60
  text "X" at 12956.46,3673.64 h60
  text "NC_DRILL FILES" at 13093.46,3673.64 h60
  text "PTH MIN COPPER THICKNESS:" at 11407.23,3515.64 h60
  text "X" at 12757.46,3515.64 h60
  text "1MIL" at 12894.46,3515.64 h60
  text "OTHER" at 13391.46,3515.64 h60
  text "BOARD FINISH:" at 11332.46,3356.64 h60
  text "SILKSCREEN:" at 11487.68,3238.64 h60
  text "X" at 12436.46,3238.64 h60
  text "TOP" at 12562.46,3238.64 h60
  text "X" at 12946.46,3238.64 h60
  text "BOTTOM" at 13073.46,3238.64 h60
  text "SILKSCREEN COLOR:" at 11487.68,3071.64 h60
  text "X" at 12435.42,3071.64 h60
  text "WHITE" at 12562.46,3071.64 h60
  text "OTHER" at 13073.46,3071.64 h60
  text "SOLDER RESIST COLOR:" at 11487.68,2901.64 h60
  text "X" at 12055.42,2742.44 h60
  text "GREEN" at 12182.46,2742.44 h60
  text "BLUE" at 12773.46,2742.44 h60
  text "OTHER" at 13311.46,2742.44 h60
  text "IMMERSION GOLD (ENIG)" at 12393.46,2553.92 h60
  text "ENEPIG" at 13731,2550.64 h60
  text "SURFACE FINISH:" at 11332.46,2549.64 h60
  text "X" at 12206.51,2549.64 h60
  text "IMM. TIN/SILVER OR EQUIV" at 11662,2392.64 h60
  text "OTHER" at 13093.46,2392.64 h60
  text "ARRAY/PANEL:" at 11332.46,2213.64 h60
  text "CUT AND TRIM PER MECH LAYER 1" at 12393.46,2209.35 h60
  text "N.C. ROUTE" at 12393.46,2057.64 h60
  text "X" at 13072.46,2057.64 h60
  text "V. SCORE" at 13259.46,2057.64 h60
  text "CERTIFICATION:" at 11332.46,1920.64 h60
  text "MATERIALS AND WORKMANSHIP FOR ALL PCBS" at 12057.46,1920.64 h60
  text "TO MEET OR EXCEED THE REQUIREMENTS OF:" at 12057.46,1822.64 h60
  text "X" at 11683.96,1686.13 h60
  text "ANSI IPC-A-600F CLASS ->" at 11822.96,1686.13 h60
  text "X" at 13462.02,1686.13 h60
  text "2" at 13580.96,1686.14 h60
  text "1" at 13265.96,1684.64 h60
  text "3" at 13934.96,1684.64 h60
  text "X" at 11686.02,1526.64 h60
  text "UL 94V-0" at 11822.96,1526.64 h60
  text "X" at 12498.02,1526.64 h60
  text "RoHS" at 12634.96,1526.64 h60
  text "OTHER" at 13279.36,1526.64 h60
  text "PER ORDER" at 13676.42,1526.64 h60
  text "ADDITIONAL REQUIREMENTS:" at 11332.46,1385.64 h60
  text "MICROSECTION:" at 11407.23,1270.64 h60
  text "YES" at 12312.96,1270.64 h60
  text "REQUIRED" at 13174.46,1114.49 h60
  text "BARE BOARD ELEC. TEST:" at 11407.23,1111.64 h60
  text "NONE" at 12712.96,1111.64 h60
  text "X" at 13047.46,1111.64 h60
  text "PER ORDER" at 13766.46,1111.64 h60
  text "MANUFACTURER'S UL:" at 11407.23,954.64 h60
  text "RAIL" at 12572.96,950.35 h60
  text "METAL" at 13064.77,950.35 h60
  text "X" at 13440,950 h60
  text "SILK" at 13576.46,950.35 h60
  text ".Layer_Name" at 577,-858.49 h60
M11 Gerber Information:
  lines w10: -292,-930.17 6308,-930.17 ; -292,-726.83 6310,-726.83 ; -292,-523.5 -292,-1133.5 3713,-1133.5 6310,-1133.5 6310,-523.5 -291.5,-523.5 -291.5,-1133.5 1284,-1133.5 ; 2173,-1133.5 2173,-523.5 ; 3440,-726.83 3440,-523.5 ; 4280,-726.83 4280,-523.5 ; 4902,-1140 4902,-937.17
  text "ALL ARTWORK VIEWED FROM TOP SIDE" at -228.5,-655.67 h60
  text "BOARD #:" at 2248,-655.67 h60
  text ".PRJ_Number" at 2793.5,-655.67 h60
  text "REV:" at 3638,-655.67 h60
  text ".PCB_Rev" at 3929.5,-655.67 h60
  text "SVN REV:" at 4476,-655.67 h60
  text ".VersionControl_RevNumber" at 4982,-655.67 h60
  text "LAYER NAME =" at -228.5,-858.49 h60
  text "PLOT NAME =" at -228.5,-1064.34 h60
  text ".plot_File_Name" at 577,-1064.34 h60
  text "GENERATED    :" at 2250,-1064.34 h60
  text ".Print_Date" at 3119.5,-1064.34 h60
  text ".Print_Time" at 3848.5,-1064.34 h60
  text "TEXAS INSTRUMENTS" at 5113,-1064.34 h60
M12 Stackup:
  lines w6: 11360,7460 13910,7460 ; 11360,7564.4 13910,7564.4 ; 11300,6975 ccw(c11334,6975) 11334,6941 13936,6941 ccw(c13936,6975) 13970,6975 13970,7681 ccw(c13936,7681) 13936,7715 11334,7715 ccw(c11334,7681) 11300,7681 11300,6975
  text "The Stackup Legend below this is static." at 11605.5,7874.5 h60
  text "If you change the stackup, update the Legend." at 11615.5,7784.5 h60
  text "Layer Stack Up Detail for: Ref_Design.PcbDoc" at 11360,7597.1 h57
  text "Layer" at 11360,7525.4 h24
  text "Gerber" at 12255.81,7525.4 h24
  text "Copper" at 12819.33,7525.4 h24
  text "Dielectric" at 13422.04,7525.4 h24
  text "Name" at 11360,7477.4 h24
  text "Document" at 12255.81,7477.4 h24
  text "Thickness" at 12819.33,7477.4 h24
  text "Material" at 13422.04,7477.4 h24
  text "Top Solder Mask" at 11360,7384.44 h34
  text "(.GTS)" at 12255.81,7384.44 h34
  text "Solder Resist" at 13422.04,7384.44 h34
  text "Top Layer" at 11360,7287.69 h34
  text "(.GTL)" at 12255.81,7287.69 h34
  text "1.4mil" at 12819.33,7287.69 h34
  text "FR-4" at 13422.04,7239.31 h34
  text "Bottom Layer" at 11360,7190.94 h34
  text "(.GBL)" at 12255.81,7190.94 h34
  text "1.4mil" at 12819.33,7190.94 h34
  text "Bottom Solder Mask" at 11360,7094.19 h34
  text "(.GBS)" at 12255.81,7094.19 h34
  text "Solder Resist" at 13422.04,7094.19 h34
  text ".Layer_Name" at 577,-858.49 h60
M13 Component Bodies Top:
  text ".Layer_Name" at 577,-858.49 h60
M14 Component Bodies Bottom:
  text ".Layer_Name" at 577,-858.49 h60
M15 Courtyards Top:
  text ".Layer_Name" at 577,-858.49 h60
M16 Courtyards Bottom:
  text ".Layer_Name" at 577,-858.49 h60
Drill Drawing:
  text ".legend" at 6864,1454 h60
  text "Drill Table" at 6868,1358 h60
  text ".Layer_Name" at 577,-858.49 h60

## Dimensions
0,0 to 0,2150 on M2 Board Dimensions
0,-410.5 to 1000,-410.5 on M2 Board Dimensions
6250,0 to 0,0 on M2 Board Dimensions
